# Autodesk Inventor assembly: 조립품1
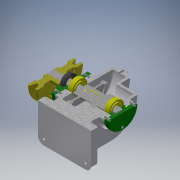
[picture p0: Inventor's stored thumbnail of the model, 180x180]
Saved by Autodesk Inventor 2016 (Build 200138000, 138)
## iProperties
Created: 2017-11
Part Number: 조립품1
Material: 일반
Document SubType Name: Assembly
Designer: 605-03
Author: 605-03
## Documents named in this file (14)
- C:\Users\605-03\Desktop\471107V1025\조립품1.iam
- C:\Users\605-03\Desktop\471107V1025\본체.ipt
- C:\Users\605-03\Desktop\471107V1025\V-벨트풀리.ipt
- C:\Users\605-03\Desktop\471107V1025\뒤커버.ipt
- C:\Users\605-03\Desktop\471107V1025\멈춤나사 - M4 x 10.ipt
- 멈춤나사 - M4 x 10.ipt
- C:\Users\605-03\Desktop\471107V1025\베어링 6002.ipt
- C:\Users\605-03\Desktop\471107V1025\볼트 M3 x 8.ipt
- C:\Users\605-03\Desktop\471107V1025\스퍼기어.ipt
- C:\Users\605-03\Desktop\471107V1025\앞커버.ipt
- C:\Users\605-03\Desktop\471107V1025\오일 실 15 30 7.ipt
- C:\Users\605-03\Desktop\471107V1025\축.ipt
- C:\Users\605-03\Desktop\471107V1025\키 - 5 x 5 x 18.ipt
- C:\Users\605-03\Desktop\471107V1025\키 - 6 x 6 x 22.ipt
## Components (1 placed, 1 different names)
1. V-벨트풀리:1
